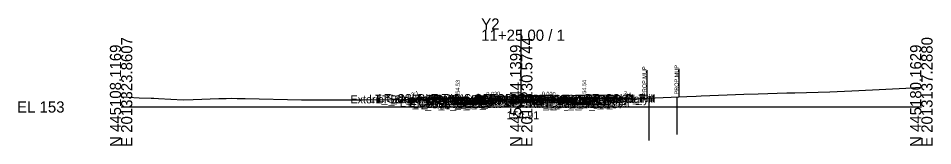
# Model space of a CAD drawing. Extents: x -26 to 203, y -10 to 6017.
# Drawn here: x -25.7 to 202.8, y 2490.3 to 2522.2 of the extents above; entities that cross this region are included whole.
import ezdxf

# ---------------------------------------------------------------- set-up
doc = ezdxf.new("R2010")
doc.units = 0
for name, color, linetype in [('Default', 7, 'Continuous'), ('Exist CMT Pavement', 7, 'Continuous'), ('Exist Cross Section Cell', 7, 'Continuous'), ('Exist XS Center Line Elevation Label', 7, 'Continuous'), ('Exist XS Ground Line', 7, 'Continuous'), ('Prop CMT Conc Surface', 7, 'Continuous'), ('Prop CMT Concrete Structures', 7, 'Continuous'), ('Prop CMT Pvmt Course 1', 7, 'Continuous'), ('Prop CMT Pvmt Course 1 CG', 7, 'Continuous'), ('Prop CMT Pvmt Course 2', 7, 'Continuous'), ('Prop CMT Pvmt Course 3', 7, 'Continuous'), ('Prop CMT Pvmt Surface', 7, 'Continuous'), ('Prop CMT Pvmt Wedge Surface 1', 7, 'Continuous'), ('Prop CMT Pvmt Wedge Surface 2', 7, 'Continuous'), ('Prop CMT Pvmt Wedge Surface 3', 7, 'Continuous'), ('Prop CMT Slope Grass', 7, 'Continuous'), ('Prop CMT Subgrade Earthwork', 7, 'Continuous'), ('Prop XS Earthwork Shape', 7, 'Continuous'), ('Prop XS Hydro Elevations', 7, 'Continuous'), ('Prop XS Label Text', 7, 'Continuous'), ('Prop XS SE Text', 7, 'Continuous'), ('Prop XS Side Slope Text', 7, 'Continuous'), ('Scratch_Level_0', 7, 'Continuous'), ('Scratch_Level_1', 7, 'Continuous')]:
    doc.layers.add(name, color=color, linetype=linetype)

msp = doc.modelspace()

# ---------------------------------------------------------------- linework, layer by layer
at = {"layer": 'Exist CMT Pavement'}
msp.add_lwpolyline([(93.06, 2501.97), (100, 2501.91), (102.71, 2501.89), (103.06, 2501.89), (112.19, 2502), (112.72, 2502)], dxfattribs=at)
at = {"layer": 'Exist Cross Section Cell'}
for p, q in [((100, 2500), (100, 2519.35)), ((0, 2500), (100, 2500)), ((100, 2500), (200, 2500))]:
    msp.add_line(p, q, dxfattribs=at)
at = {"layer": 'Exist XS Ground Line'}
msp.add_lwpolyline([(0, 2502.51), (1.8, 2502.44), (4.52, 2502.31), (7.48, 2502.2), (8.19, 2502.17), (9.35, 2502.12), (15.53, 2501.82), (18.04, 2501.89), (24.45, 2502.09), (25.8, 2502.14), (26.29, 2502.15), (27.66, 2502.17), (29.01, 2502.14), (30.04, 2502.12), (31.02, 2502.1), (45.08, 2501.8), (46.03, 2501.77), (46.75, 2501.77), (55.75, 2501.81), (57.1, 2501.82), (57.82, 2501.82), (59.17, 2501.81), (60.33, 2501.83), (69.89, 2501.9), (74.13, 2501.87), (82.32, 2502.1), (87.74, 2502.23), (91.09, 2502.23), (93.06, 2501.97), (100, 2501.91), (102.71, 2501.89), (103.06, 2501.89), (112.19, 2502), (112.72, 2502), (114.78, 2502.27), (115.08, 2502.26), (120.13, 2502.05), (125.36, 2502.05), (127.6, 2502.05), (141.4, 2502.64), (143.74, 2502.74), (144.94, 2502.78), (151.47, 2503.02), (155.66, 2503.18), (159.2, 2503.3), (166.38, 2503.51), (168.38, 2503.56), (177.1, 2503.82), (182.59, 2504.02), (187.82, 2504.25), (196.14, 2504.72), (198.54, 2504.86), (200, 2504.92)], dxfattribs=at)
at = {"layer": 'Prop CMT Conc Surface'}
for points in [[(84.14, 2501.53), (84.14, 2502.03), (83.64, 2502.03)], [(86.14, 2501.65), (84.14, 2501.53)], [(113.74, 2501.66), (115.74, 2501.54)], [(115.74, 2501.54), (115.74, 2502.04), (116.24, 2502.04)]]:
    msp.add_lwpolyline(points, dxfattribs=at)
at = {"layer": 'Prop CMT Concrete Structures'}
for points in [[(86.14, 2501.65), (84.14, 2501.53), (84.14, 2502.03), (83.64, 2502.03)], [(83.64, 2502.03), (83.64, 2501.02), (86.14, 2501.07)], [(86.14, 2501.07), (86.14, 2501.65)], [(113.74, 2501.66), (115.74, 2501.54), (115.74, 2502.04), (116.24, 2502.04)], [(116.24, 2502.04), (116.24, 2501.02), (113.74, 2501.07)], [(113.74, 2501.07), (113.74, 2501.66)]]:
    msp.add_lwpolyline(points, dxfattribs=at)
at = {"layer": 'Prop CMT Pvmt Course 1'}
for points in [[(99.98, 2501.93), (86.14, 2501.65)], [(86.14, 2501.65), (86.14, 2501.4)], [(86.14, 2501.4), (93.06, 2501.54)], [(93.06, 2501.67), (99.98, 2501.81)], [(93.06, 2501.54), (93.06, 2501.67)], [(99.98, 2501.68), (99.98, 2501.93)], [(99.98, 2501.93), (113.74, 2501.66)], [(99.98, 2501.68), (99.98, 2501.93)], [(99.98, 2501.81), (99.98, 2501.68), (99.98, 2501.68)], [(112.73, 2501.55), (99.98, 2501.81)], [(99.98, 2501.81), (99.98, 2501.68), (99.98, 2501.68)], [(112.73, 2501.43), (112.73, 2501.55)], [(113.74, 2501.41), (112.73, 2501.43)], [(113.74, 2501.66), (113.74, 2501.41)]]:
    msp.add_lwpolyline(points, dxfattribs=at)
at = {"layer": 'Prop CMT Pvmt Course 1 CG'}
for points in [[(86.14, 2501.07), (83.14, 2501.01), (82.8, 2500.67)], [(82.8, 2500.67), (86.14, 2500.74)], [(86.14, 2500.74), (86.14, 2501.07)], [(113.74, 2501.07), (116.74, 2501.01), (117.08, 2500.67)], [(113.74, 2500.74), (113.74, 2501.07)], [(117.08, 2500.67), (113.74, 2500.74)]]:
    msp.add_lwpolyline(points, dxfattribs=at)
at = {"layer": 'Prop CMT Pvmt Course 2'}
for points in [[(91.08, 2501.5), (86.14, 2501.4)], [(86.14, 2501.4), (86.14, 2501.07)], [(86.14, 2501.07), (91.08, 2501.17)], [(93.06, 2501.21), (93.06, 2501.54)], [(112.73, 2501.09), (112.73, 2501.43)], [(112.73, 2501.43), (113.74, 2501.41)], [(113.74, 2501.07), (112.73, 2501.09)], [(113.74, 2501.41), (113.74, 2501.07)]]:
    msp.add_lwpolyline(points, dxfattribs=at)
at = {"layer": 'Prop CMT Pvmt Course 3'}
for points in [[(93.06, 2501.21), (86.14, 2501.07)], [(86.14, 2501.07), (86.14, 2500.74)], [(86.14, 2500.74), (93.06, 2500.88)], [(93.06, 2500.88), (93.06, 2501.21)], [(112.73, 2501.09), (113.74, 2501.07)], [(112.73, 2500.76), (112.73, 2501.09)], [(113.74, 2500.74), (112.73, 2500.76)], [(113.74, 2501.07), (113.74, 2500.74)]]:
    msp.add_lwpolyline(points, dxfattribs=at)
at = {"layer": 'Prop CMT Pvmt Surface'}
for points in [[(99.98, 2501.93), (86.14, 2501.65)], [(99.98, 2501.93), (113.74, 2501.66)]]:
    msp.add_lwpolyline(points, dxfattribs=at)
at = {"layer": 'Prop CMT Pvmt Wedge Surface 1'}
for points in [[(86.14, 2501.4), (86.14, 2501.65)], [(91.08, 2501.5), (86.14, 2501.4)], [(99.98, 2501.81), (93.06, 2501.67)], [(93.06, 2501.67), (93.06, 2501.54)], [(99.98, 2501.81), (112.73, 2501.55)], [(112.73, 2501.55), (112.73, 2501.43)], [(112.73, 2501.43), (113.74, 2501.41)], [(113.74, 2501.41), (113.74, 2501.66)]]:
    msp.add_lwpolyline(points, dxfattribs=at)
at = {"layer": 'Prop CMT Pvmt Wedge Surface 2'}
for points in [[(86.14, 2501.4), (86.14, 2501.65)], [(99.98, 2501.68), (93.06, 2501.54)], [(99.98, 2501.68), (113.74, 2501.41)], [(113.74, 2501.41), (113.74, 2501.66)]]:
    msp.add_lwpolyline(points, dxfattribs=at)
at = {"layer": 'Prop CMT Pvmt Wedge Surface 3'}
for points in [[(86.14, 2501.07), (86.14, 2501.65)], [(99.98, 2501.35), (93.06, 2501.21)], [(99.98, 2501.35), (113.74, 2501.07)], [(113.74, 2501.07), (113.74, 2501.66)]]:
    msp.add_lwpolyline(points, dxfattribs=at)
at = {"layer": 'Prop CMT Slope Grass'}
for points in [[(83.64, 2502.03), (74.14, 2502.22), (73.1, 2501.88)], [(116.24, 2502.04), (125.74, 2502.23), (126.27, 2502.05)]]:
    msp.add_lwpolyline(points, dxfattribs=at)
at = {"layer": 'Prop CMT Subgrade Earthwork'}
msp.add_line((93.06, 2501.97), (93.06, 2500.88), dxfattribs=at)
for points in [[(86.14, 2500.74), (82.8, 2500.67), (81.39, 2502.08)], [(93.06, 2500.88), (86.14, 2500.74)], [(112.73, 2500.76), (112.72, 2502)], [(112.73, 2500.76), (113.74, 2500.74)], [(113.74, 2500.74), (117.08, 2500.67), (118.48, 2502.08)]]:
    msp.add_lwpolyline(points, dxfattribs=at)
at = {"layer": 'Prop XS Earthwork Shape'}
for points in [[(81.39, 2502.08), (74.14, 2502.22), (73.1, 2501.88), (74.13, 2501.87)], [(81.39, 2502.08), (74.14, 2502.22), (73.1, 2501.88), (74.13, 2501.87)], [(81.39, 2502.08), (74.14, 2502.22), (73.1, 2501.88), (74.13, 2501.87)], [(81.39, 2502.08), (74.14, 2502.22), (73.1, 2501.88), (74.13, 2501.87)], [(91.09, 2502.23), (93.06, 2501.97), (93.06, 2501.79), (86.14, 2501.65), (84.14, 2501.53), (84.14, 2502.03), (83.64, 2502.03), (81.39, 2502.08), (82.32, 2502.1), (87.74, 2502.23)], [(91.09, 2502.23), (93.06, 2501.97), (93.06, 2501.79), (86.14, 2501.65), (84.14, 2501.53), (84.14, 2502.03), (83.64, 2502.03), (81.39, 2502.08), (82.32, 2502.1), (87.74, 2502.23)], [(91.09, 2502.23), (93.06, 2501.97), (93.06, 2501.79), (86.14, 2501.65), (84.14, 2501.53), (84.14, 2502.03), (83.64, 2502.03), (81.39, 2502.08), (82.32, 2502.1), (87.74, 2502.23)], [(82.32, 2502.1), (87.74, 2502.23), (91.09, 2502.23), (93.06, 2501.97), (93.06, 2501.79), (86.14, 2501.65), (84.14, 2501.53), (84.14, 2502.03), (83.64, 2502.03), (81.39, 2502.08)], [(82.8, 2500.67), (81.39, 2502.08), (83.64, 2502.03), (83.64, 2501.02), (86.14, 2501.07), (86.14, 2501.65), (93.06, 2501.79), (93.06, 2500.88), (86.14, 2500.74)], [(86.14, 2501.07), (86.14, 2501.65), (93.06, 2501.79), (93.06, 2500.88), (86.14, 2500.74), (82.8, 2500.67), (81.39, 2502.08), (83.64, 2502.03), (83.64, 2501.02)], [(82.8, 2500.67), (81.39, 2502.08), (83.64, 2502.03), (83.64, 2501.02), (86.14, 2501.07), (86.14, 2501.65), (93.06, 2501.79), (93.06, 2500.88), (86.14, 2500.74)], [(86.14, 2501.07), (86.14, 2501.65), (93.06, 2501.79), (93.06, 2500.88), (86.14, 2500.74), (82.8, 2500.67), (81.39, 2502.08), (83.64, 2502.03), (83.64, 2501.02)], [(86.14, 2501.07), (86.14, 2501.65), (84.14, 2501.53), (84.14, 2502.03), (83.64, 2502.03), (83.64, 2501.02)], [(86.14, 2501.07), (86.14, 2501.65), (84.14, 2501.53), (84.14, 2502.03), (83.64, 2502.03), (83.64, 2501.02)], [(86.14, 2501.07), (86.14, 2501.65), (84.14, 2501.53), (84.14, 2502.03), (83.64, 2502.03), (83.64, 2501.02)], [(86.14, 2501.07), (86.14, 2501.65), (84.14, 2501.53), (84.14, 2502.03), (83.64, 2502.03), (83.64, 2501.02)], [(99.32, 2501.92), (93.06, 2501.79), (93.06, 2501.97)], [(99.32, 2501.92), (93.06, 2501.79), (93.06, 2501.97)], [(99.32, 2501.92), (93.06, 2501.79), (93.06, 2501.97)], [(99.32, 2501.92), (93.06, 2501.79), (93.06, 2501.97)], [(103.06, 2501.89), (112.19, 2502), (112.72, 2502), (112.72, 2501.68), (101.71, 2501.9), (102.71, 2501.89)], [(101.71, 2501.9), (112.72, 2501.68), (112.72, 2502), (112.19, 2502), (103.06, 2501.89), (102.71, 2501.89)], [(103.06, 2501.89), (112.19, 2502), (112.72, 2502), (112.72, 2501.68), (101.71, 2501.9), (102.71, 2501.89)], [(103.06, 2501.89), (112.19, 2502), (112.72, 2502), (112.72, 2501.68), (101.71, 2501.9), (102.71, 2501.89)], [(115.74, 2501.54), (115.74, 2502.04), (116.24, 2502.04), (118.48, 2502.08), (119.05, 2502.09), (115.08, 2502.26), (114.78, 2502.27), (112.72, 2502), (112.72, 2501.68), (113.74, 2501.66)], [(116.24, 2502.04), (118.48, 2502.08), (119.05, 2502.09), (115.08, 2502.26), (114.78, 2502.27), (112.72, 2502), (112.72, 2501.68), (113.74, 2501.66), (115.74, 2501.54), (115.74, 2502.04)], [(115.74, 2501.54), (115.74, 2502.04), (116.24, 2502.04), (118.48, 2502.08), (119.05, 2502.09), (115.08, 2502.26), (114.78, 2502.27), (112.72, 2502), (112.72, 2501.68), (113.74, 2501.66)], [(115.74, 2501.54), (115.74, 2502.04), (116.24, 2502.04), (118.48, 2502.08), (119.05, 2502.09), (115.08, 2502.26), (114.78, 2502.27), (112.72, 2502), (112.72, 2501.68), (113.74, 2501.66)], [(116.24, 2502.04), (116.24, 2501.02), (113.74, 2501.07), (113.74, 2501.66), (112.72, 2501.68), (112.73, 2500.76), (113.74, 2500.74), (117.08, 2500.67), (118.48, 2502.08)], [(116.24, 2502.04), (118.48, 2502.08), (117.08, 2500.67), (113.74, 2500.74), (112.73, 2500.76), (112.72, 2501.68), (113.74, 2501.66), (113.74, 2501.07), (116.24, 2501.02)], [(116.24, 2502.04), (116.24, 2501.02), (113.74, 2501.07), (113.74, 2501.66), (112.72, 2501.68), (112.73, 2500.76), (113.74, 2500.74), (117.08, 2500.67), (118.48, 2502.08)], [(116.24, 2502.04), (116.24, 2501.02), (113.74, 2501.07), (113.74, 2501.66), (112.72, 2501.68), (112.73, 2500.76), (113.74, 2500.74), (117.08, 2500.67), (118.48, 2502.08)], [(116.24, 2502.04), (116.24, 2501.02), (113.74, 2501.07), (113.74, 2501.66), (115.74, 2501.54), (115.74, 2502.04)], [(116.24, 2502.04), (116.24, 2501.02), (113.74, 2501.07), (113.74, 2501.66), (115.74, 2501.54), (115.74, 2502.04)], [(116.24, 2502.04), (116.24, 2501.02), (113.74, 2501.07), (113.74, 2501.66), (115.74, 2501.54), (115.74, 2502.04)], [(116.24, 2502.04), (116.24, 2501.02), (113.74, 2501.07), (113.74, 2501.66), (115.74, 2501.54), (115.74, 2502.04)], [(125.36, 2502.05), (126.27, 2502.05), (125.74, 2502.23), (119.05, 2502.09), (120.13, 2502.05)], [(125.36, 2502.05), (126.27, 2502.05), (125.74, 2502.23), (119.05, 2502.09), (120.13, 2502.05)], [(125.36, 2502.05), (126.27, 2502.05), (125.74, 2502.23), (119.05, 2502.09), (120.13, 2502.05)], [(125.36, 2502.05), (126.27, 2502.05), (125.74, 2502.23), (119.05, 2502.09), (120.13, 2502.05)]]:
    msp.add_lwpolyline(points, close=True, dxfattribs=at)
at = {"layer": 'Prop XS Label Text'}
for p, q in [((139.41, 2509.55), (139.41, 2502.55)), ((131.39, 2509.21), (131.39, 2502.21))]:
    msp.add_line(p, q, dxfattribs=at)
at = {"layer": 'Scratch_Level_1'}
for p, q in [((138.91, 2502.53), (138.91, 2493.08)), ((131.9, 2502.23), (131.9, 2491.62))]:
    msp.add_line(p, q, dxfattribs=at)

# ---------------------------------------------------------------- texts
at = {"layer": 'Default'}
msp.add_text('-', height=0.0001, dxfattribs=at).set_placement((0, 2500))
at = {"layer": 'Exist Cross Section Cell'}
for s, p in [('Y2', (90, 2519.35)), ('11+25.00 / 1', (90, 2516.55)), ('EL 153', (-26, 2498.6))]:
    msp.add_text(s, height=2.8, dxfattribs=at).set_placement(p)
for s, p in [('E 2013323.8607', (2.8, 2490)), ('E 2013230.5744', (102.8, 2490)), ('E 2013137.2880', (202.8, 2490)), ('N 445108.1169', (0, 2490)), ('N 445144.1399', (100, 2490)), ('N 445180.1629', (200, 2490))]:
    msp.add_text(s, height=2.8, rotation=90, dxfattribs=at).set_placement(p)
at = {"layer": 'Exist XS Center Line Elevation Label'}
msp.add_text('154.91', height=2, dxfattribs=at).set_placement((96.32, 2496.91))
at = {"layer": 'Prop XS Hydro Elevations'}
for s, p in [('154.53', (84.64, 2502.53)), ('154.54', (116.24, 2502.54))]:
    msp.add_text(s, height=1, rotation=90, dxfattribs=at).set_placement(p)
at = {"layer": 'Prop XS Label Text'}
for p in [(131.29, 2502.78), (139.31, 2503.13)]:
    msp.add_text('PROP.MUP', height=1, rotation=90, dxfattribs=at).set_placement(p)
at = {"layer": 'Prop XS SE Text'}
for rotation, p in [(1.1457, (91.29, 2502.76)), (358.8541, (105.13, 2502.83))]:
    msp.add_text('0.020', height=1, rotation=rotation, dxfattribs=at).set_placement(p)
at = {"layer": 'Prop XS Side Slope Text'}
for rotation, p in [(18.4317, (72.68, 2502.53)), (341.5651, (125.49, 2503.1))]:
    msp.add_text('3:1', height=1, rotation=rotation, dxfattribs=at).set_placement(p)
at = {"layer": 'Scratch_Level_0'}
for s, p in [('Exterior Boundary', (57.34, 2500.91)), ('LT_Sub_Trench_Out_DLT', (61.96, 2501.08)), ('LT_Slope_Fill', (63.71, 2500.91)), ('LT_CSLP_Pnt', (64.32, 2501.22)), ('LT_CG_Top_Face', (71.4, 2501.03)), ('LT_CG_Top_BOC', (71.93, 2501.03)), ('LT_CG_Top_Gut', (72.38, 2500.53)), ('LT_PV_Sub_Tie_Out', (76.04, 2501.22)), ('LT_PV2_OEOT', (76.32, 2500.4)), ('LT_PV1_OEOT', (76.88, 2500.65)), ('LT_PV_OEEOP_EG', (78.62, 2501.22)), ('LT_PV2_OEEOP', (80.38, 2500.5)), ('LT_PV1_OEEOP', (80.95, 2500.63)), ('RT_PV_IEEOP_EG', (88.12, 2500.88)), ('LT_PV_IEEOP_EG', (88.17, 2500.88)), ('RT_PV2_IEEOP', (89.89, 2500.68)), ('LT_PV2_IEEOP', (89.93, 2500.68)), ('RT_PV1_IEEOP', (90.45, 2500.81)), ('LT_PV1_IEEOP', (90.5, 2500.81)), ('PV2_PGL', (93.89, 2500.68)), ('PV1_PGL', (94.45, 2500.93)), ('RT_PV_Sub_Tie_Out', (97.62, 2500.98)), ('RT_Sub_Trench_Out_DLT', (99, 2501.08)), ('RT_PV_OEEOP_EG', (100.23, 2500.98)), ('RT_PV2_OEEOP', (101.99, 2500.43)), ('RT_PV1_OEEOP', (102.56, 2500.55)), ('RT_CG_Top_Face', (102.95, 2501.04)), ('RT_PV2_OEOT', (103.86, 2500.41)), ('RT_CG_Top_Gut', (103.92, 2500.54)), ('RT_PV1_OEOT', (104.43, 2500.66)), ('RT_CG_Top_BOC', (104.47, 2501.04)), ('Exterior Boundary', (110.42, 2501.04)), ('RT_CSLP_Pnt', (115.86, 2501.23)), ('RT_Slope_Fill', (116.75, 2501.04)), ('LT_CG1_Shelf_Out', (69.69, 2500.01)), ('LT_CG_Bot_BOC', (71.96, 2500.02)), ('LT_Sub_OEOP', (72.91, 2499.67)), ('LT_CG_Bot_IE', (76.06, 2500.07)), ('LT_Sub_OEOT', (76.22, 2499.74)), ('LT_PV3_OEOT', (76.32, 2500.07)), ('LT_Sub_OEEOP', (80.29, 2499.84)), ('LT_PV3_OEEOP', (80.38, 2500.17)), ('RT_PV3_IEEOP', (89.89, 2500.35)), ('LT_PV3_IEEOP', (89.93, 2500.35)), ('RT_Sub_OEEOP', (101.9, 2499.76)), ('RT_PV3_OEEOP', (101.99, 2500.09)), ('RT_CG1_Shelf_Out', (103.24, 2500.01)), ('RT_CG_Bot_IE', (103.6, 2500.07)), ('RT_Sub_OEOT', (103.77, 2499.74)), ('RT_PV3_OEOT', (103.86, 2500.07)), ('RT_CG_Bot_BOC', (104.5, 2500.02)), ('RT_Sub_OEOP', (107.14, 2499.67))]:
    msp.add_text(s, height=2, dxfattribs=at).set_placement(p)

doc.saveas('drawing.dxf')
